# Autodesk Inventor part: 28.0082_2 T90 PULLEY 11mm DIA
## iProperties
Created: 2006-12
Document SubType Name: Modeling
Designer: Andy Moles
Part Number: 28.0082_2 T90 PULLEY 11mm DIA
Material: Aluminum-6061
Density: 2.71 g/cm^3
Author: Andy Moles
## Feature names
1. Extrusion1
2. Extrusion3
3. Extrusion4
4. Extrusion6
5. Mirror1
6. Extrusion7
7. Chamfer1
